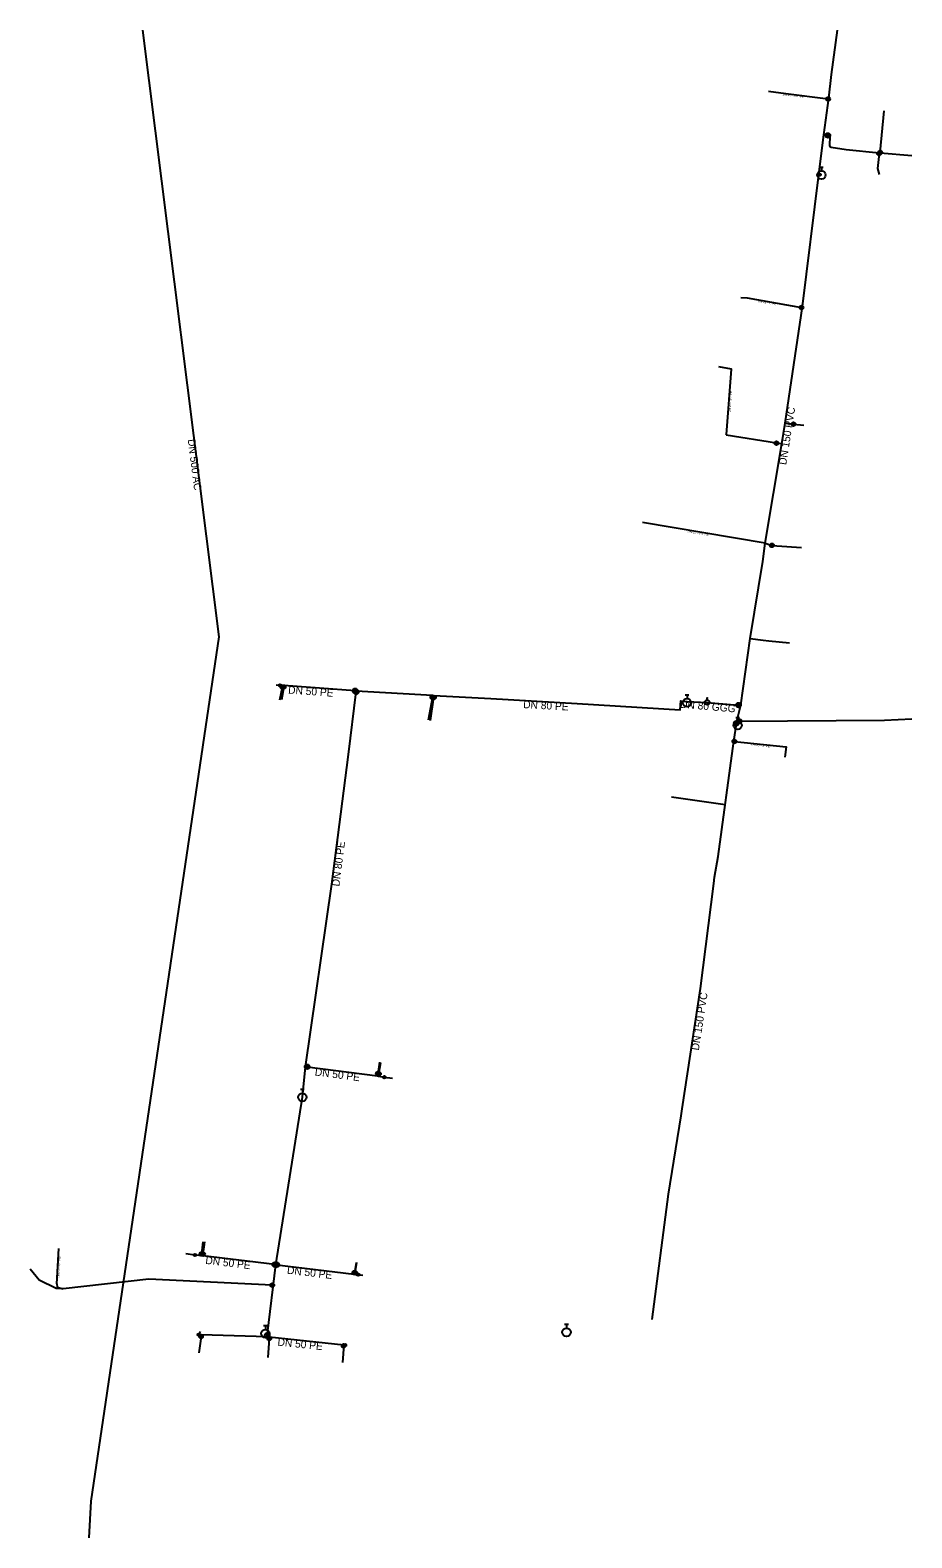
# Model space of a CAD drawing. Extents: x -463725 to -463539, y -1094944 to -1094626.
import ezdxf

# ---------------------------------------------------------------- set-up
doc = ezdxf.new("R2010")
doc.units = 0
for name, color, linetype in [('_hydrantova_odbocka_', 7, 'Continuous'), ('_kalosvod_', 7, 'Continuous'), ('_pripojka_prevzato_z_dokumentace_', 7, 'Continuous'), ('_pripojka_priblizne_', 7, 'Continuous'), ('_voda_provozovana_prevzato_z_dokumentace_', 7, 'Continuous'), ('_voda_smvak_prevzato_z_dokumentace_', 7, 'Continuous'), ('_voda_smvak_priblizne_', 7, 'Continuous'), ('Default', 7, 'Continuous'), ('MoLevel 2', 7, 'Continuous'), ('MoLevel 27', 7, 'Continuous'), ('MoLevel 28', 7, 'Continuous'), ('MoLevel 32', 7, 'Continuous'), ('MoLevel 38', 7, 'Continuous'), ('MoLevel 46', 7, 'Continuous'), ('MoLevel 48', 7, 'Continuous'), ('MoLevel 53', 7, 'Continuous'), ('MoLevel 55', 7, 'Continuous')]:
    doc.layers.add(name, color=color, linetype=linetype)

# ---------------------------------------------------------------- blocks, each defined once
blk = doc.blocks.new('_uzaver_')
at = {"layer": 'Default'}
for p, q in [((-0.000035, -0.000035), (0.000035, 0.000035)), ((0.000035, -0.000035), (-0.000035, 0.000035))]:
    blk.add_line(p, q, dxfattribs=at)
for radius in [0.00005, 0.0000025]:
    blk.add_circle((0, 0), radius, dxfattribs=at)
blk = doc.blocks.new('_uzaver_pripojka_')
at = {"layer": 'Default'}
for p, q in [((-0.000035, -0.000035), (0.000035, 0.000035)), ((0.000035, -0.000035), (-0.000035, 0.000035))]:
    blk.add_line(p, q, dxfattribs=at)
for radius in [0.00005, 0.0000025]:
    blk.add_circle((0, 0), radius, dxfattribs=at)
blk = doc.blocks.new('_hydrant_voda_')
at = {"layer": 'Default'}
for p, q in [((-0.000023, 0.000095), (0.000023, 0.000095)), ((0, 0.000095), (0, 0.00005))]:
    blk.add_line(p, q, dxfattribs=at)
blk.add_circle((0, 0), 0.00005, dxfattribs=at)
blk = doc.blocks.new('_vzdusnik_')
at = {"layer": 'Default'}
blk.add_line((0, 0.000095), (0.00001, 0.00008), dxfattribs=at)
blk.add_lwpolyline([(0, 0.00005), (0, 0.000095), (-0.00001, 0.00008)], dxfattribs=at)
blk.add_circle((0, 0), 0.00005, dxfattribs=at)

msp = doc.modelspace()

# ---------------------------------------------------------------- linework, layer by layer
at = {"layer": '_hydrantova_odbocka_'}
for p, q in [((-463586.45, -1094767.8), (-463586.43, -1094767.5)), ((-463674.74, -1094900.54), (-463675.17, -1094900.52))]:
    msp.add_line(p, q, dxfattribs=at)
for points in [[(-463558.72, -1094656.64), (-463558.51, -1094656.66), (-463558.18, -1094656.74)], [(-463575.79, -1094772.54), (-463575.88, -1094772.31), (-463576.05, -1094772.27)]]:
    msp.add_lwpolyline(points, dxfattribs=at)
at = {"layer": '_kalosvod_'}
for p, q in [((-463672.11, -1094764.13), (-463672.88, -1094764.11)), ((-463650.15, -1094846.58), (-463648.43, -1094846.77)), ((-463689.98, -1094884), (-463691.88, -1094883.76)), ((-463655.64, -1094888.11), (-463654.64, -1094888.22)), ((-463689.19, -1094900.76), (-463688.81, -1094900.12)), ((-463658.41, -1094902.91), (-463657.96, -1094902.96))]:
    msp.add_line(p, q, dxfattribs=at)
at = {"layer": '_pripojka_prevzato_z_dokumentace_'}
for p, q in [((-463569.33, -1094639.1), (-463565.69, -1094639.58)), ((-463570.01, -1094734.19), (-463595.85, -1094729.87)), ((-463567.55, -1094734.76), (-463562.38, -1094735.14)), ((-463573.18, -1094754.3), (-463570.43, -1094754.63)), ((-463719.04, -1094890.09), (-463718.59, -1094882.6)), ((-463658.68, -1094902.88), (-463658.94, -1094906.64))]:
    msp.add_line(p, q, dxfattribs=at)
for points in [[(-463565.69, -1094639.58), (-463556.76, -1094640.75), (-463556.61, -1094640.58)], [(-463575.12, -1094682.49), (-463573.77, -1094682.62), (-463562.35, -1094684.61), (-463562.17, -1094684.41)], [(-463578.23, -1094711.52), (-463578.11, -1094711.33), (-463577.08, -1094697.59), (-463579.74, -1094697.09)], [(-463565.82, -1094708.98), (-463564.07, -1094709.16), (-463561.86, -1094709.41)], [(-463566.5, -1094713.31), (-463567.65, -1094713.17), (-463578.23, -1094711.52)], [(-463570.01, -1094734.19), (-463568.58, -1094734.68), (-463567.55, -1094734.76)], [(-463672.12, -1094767.15), (-463671.59, -1094764.48), (-463671.58, -1094764.16)], [(-463671.28, -1094764.18), (-463671.31, -1094764.46), (-463671.75, -1094767.2)], [(-463640, -1094766.22), (-463640.03, -1094766.65), (-463640.92, -1094771.44)], [(-463640.39, -1094771.51), (-463639.7, -1094766.67), (-463639.73, -1094766.24)], [(-463651.16, -1094843.44), (-463651.49, -1094845.82), (-463651.6, -1094846.33)], [(-463651.35, -1094846.37), (-463651.26, -1094845.89), (-463650.84, -1094843.49)], [(-463688.34, -1094881.2), (-463688.61, -1094883.77), (-463688.66, -1094884.14)], [(-463688.29, -1094884.18), (-463688.26, -1094883.81), (-463687.88, -1094881.26)], [(-463719.19, -1094891.07), (-463722.76, -1094889.29), (-463724.65, -1094886.98)], [(-463656.05, -1094885.57), (-463656.44, -1094887.71), (-463656.5, -1094888)], [(-463656.3, -1094888.03), (-463656.25, -1094887.74), (-463655.94, -1094885.58)], [(-463688.65, -1094900.78), (-463688.7, -1094901.15), (-463689.17, -1094904.59)], [(-463674.34, -1094901.25), (-463674.34, -1094901.56), (-463674.62, -1094905.58)]]:
    msp.add_lwpolyline(points, dxfattribs=at)
at = {"layer": '_pripojka_priblizne_'}
for p, q in [((-463589.75, -1094787.6), (-463578.4, -1094789.2)), ((-463717.73, -1094891.11), (-463719.19, -1094891.07))]:
    msp.add_line(p, q, dxfattribs=at)
for points in [[(-463545.81, -1094652.1), (-463545.8, -1094651.99), (-463544.94, -1094643.26)], [(-463546.02, -1094652.08), (-463546.04, -1094652.24), (-463546.35, -1094655.34), (-463545.99, -1094656.63)], [(-463570.43, -1094754.63), (-463569.22, -1094754.77), (-463564.92, -1094755.17)], [(-463576.57, -1094775.91), (-463576.49, -1094775.92), (-463565.6, -1094777.09), (-463565.85, -1094779.26)], [(-463719.04, -1094890.09), (-463718.99, -1094890.78), (-463717.73, -1094891.11)], [(-463673.5, -1094890.37), (-463673.71, -1094890.34), (-463699.66, -1094889.06), (-463717.73, -1094891.11)]]:
    msp.add_lwpolyline(points, dxfattribs=at)
at = {"layer": '_voda_provozovana_prevzato_z_dokumentace_'}
for p, q in [((-463656.25, -1094765.28), (-463656.04, -1094765.3)), ((-463656.05, -1094765.52), (-463656.04, -1094765.3)), ((-463575.62, -1094768.28), (-463575.11, -1094768.31)), ((-463667.38, -1094850.81), (-463666.74, -1094844.39)), ((-463666.74, -1094844.39), (-463666.38, -1094844.38)), ((-463672.98, -1094886.04), (-463667.38, -1094850.81)), ((-463673.19, -1094886.01), (-463672.98, -1094886.04)), ((-463672.98, -1094886.04), (-463672.76, -1094886.06)), ((-463674.79, -1094901.23), (-463674.77, -1094900.93))]:
    msp.add_line(p, q, dxfattribs=at)
for points in [[(-463656.25, -1094765.28), (-463671.28, -1094764.18), (-463671.58, -1094764.16), (-463672.11, -1094764.13)], [(-463666.74, -1094844.39), (-463661.16, -1094805.99), (-463657.64, -1094778.67), (-463656.05, -1094765.52)], [(-463656.04, -1094765.3), (-463640, -1094766.22), (-463639.73, -1094766.24), (-463627.75, -1094766.93), (-463609.56, -1094767.92), (-463587.87, -1094769.27), (-463587.72, -1094767.41), (-463586.43, -1094767.5)], [(-463586.43, -1094767.5), (-463582.24, -1094767.72), (-463575.62, -1094768.28)], [(-463666.38, -1094844.38), (-463651.6, -1094846.33), (-463651.35, -1094846.37), (-463650.15, -1094846.58)], [(-463673.19, -1094886.01), (-463688.29, -1094884.18), (-463689.98, -1094884)], [(-463674.77, -1094900.93), (-463674.74, -1094900.54), (-463672.98, -1094886.04)], [(-463672.76, -1094886.06), (-463656.5, -1094888), (-463656.3, -1094888.03), (-463655.64, -1094888.11)], [(-463674.79, -1094901.23), (-463688.65, -1094900.78), (-463689.19, -1094900.76)], [(-463674.79, -1094901.23), (-463674.34, -1094901.25), (-463658.68, -1094902.88), (-463658.41, -1094902.91)]]:
    msp.add_lwpolyline(points, dxfattribs=at)
at = {"layer": '_voda_smvak_prevzato_z_dokumentace_'}
for p, q in [((-463558.72, -1094656.64), (-463557.68, -1094648.28)), ((-463556.8, -1094648.41), (-463557.68, -1094648.28)), ((-463575.87, -1094771.39), (-463575.11, -1094768.31)), ((-463576.09, -1094772.13), (-463575.87, -1094771.39)), ((-463576.05, -1094772.27), (-463576.09, -1094772.13)), ((-463575.87, -1094771.39), (-463575.5, -1094771.68))]:
    msp.add_line(p, q, dxfattribs=at)
for points in [[(-463557.68, -1094648.28), (-463556.61, -1094640.58), (-463556.06, -1094635.59), (-463554.76, -1094626.26)], [(-463556.8, -1094648.41), (-463556.41, -1094648.54), (-463556.47, -1094650.53), (-463556.4, -1094650.75), (-463556.15, -1094650.87), (-463552.96, -1094651.37), (-463546.02, -1094652.08), (-463545.81, -1094652.1), (-463539.15, -1094652.64)], [(-463575.11, -1094768.31), (-463573.18, -1094754.3), (-463570.51, -1094738.09), (-463570.01, -1094734.19), (-463566.5, -1094713.31), (-463565.82, -1094708.98), (-463562.17, -1094684.41), (-463558.72, -1094656.64)], [(-463575.5, -1094771.68), (-463544.89, -1094771.45), (-463539.15, -1094771.16)], [(-463593.75, -1094897.6), (-463590.34, -1094871.22), (-463587.66, -1094854.7), (-463587.46, -1094853.23), (-463583.58, -1094827.92), (-463580.81, -1094805.85), (-463580.66, -1094804.49), (-463579.91, -1094800.17), (-463576.57, -1094775.91), (-463576.05, -1094772.27)]]:
    msp.add_lwpolyline(points, dxfattribs=at)
at = {"layer": '_voda_smvak_priblizne_'}
msp.add_line((-463712.25, -1094943.51), (-463711.83, -1094935.76), dxfattribs=at)
msp.add_lwpolyline([(-463711.83, -1094935.76), (-463684.88, -1094753.92), (-463700.98, -1094626.26)], dxfattribs=at)

# ---------------------------------------------------------------- block references
at = {"layer": 'MoLevel 27'}
for p, xscale, yscale in [((-463556.8, -1094648.41), 10000, 10000), ((-463672.11, -1094764.13), 5000, 5000), ((-463656.25, -1094765.28), 10000, 10000), ((-463575.62, -1094768.28), 10000, 10000), ((-463666.38, -1094844.38), 10000, 10000), ((-463650.15, -1094846.58), 5000, 5000), ((-463689.98, -1094884), 5000, 5000), ((-463673.19, -1094886.01), 10000, 10000), ((-463672.76, -1094886.06), 10000, 10000), ((-463655.64, -1094888.11), 5000, 5000), ((-463689.19, -1094900.76), 5000, 5000), ((-463658.41, -1094902.91), 5000, 5000)]:
    msp.add_blockref('_uzaver_', p, dxfattribs=dict(at, xscale=xscale, yscale=yscale))
for p, xscale, yscale, rotation in [((-463558.51, -1094656.66), 5000, 5000, -17.292449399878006), ((-463656.05, -1094765.52), 10000, 9999.999999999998, -91.26280138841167), ((-463575.5, -1094771.68), 10000.000000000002, 9999.999999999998, 0.43461422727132), ((-463576.09, -1094772.13), 10000, 9999.999999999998, -95.027543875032), ((-463674.77, -1094900.93), 9999.999999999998, 10000.000000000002, -94.56151306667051)]:
    msp.add_blockref('_uzaver_', p, dxfattribs=dict(at, xscale=xscale, yscale=yscale, rotation=rotation))
at = {"layer": 'MoLevel 28', "xscale": 17636.68430335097, "yscale": 17636.68430335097}
for p in [(-463558.18, -1094656.74), (-463586.45, -1094767.8), (-463575.79, -1094772.54), (-463667.38, -1094850.81), (-463675.17, -1094900.52), (-463611.81, -1094900.25)]:
    msp.add_blockref('_hydrant_voda_', p, dxfattribs=at)
at = {"layer": 'MoLevel 38', "xscale": 10000, "yscale": 10000}
msp.add_blockref('_vzdusnik_', (-463582.24, -1094767.72), dxfattribs=at)
at = {"layer": 'MoLevel 53', "xscale": 7999.999999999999, "yscale": 7999.999999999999}
for p in [(-463556.76, -1094640.75), (-463546.04, -1094652.24), (-463545.8, -1094651.99), (-463562.35, -1094684.61), (-463564.07, -1094709.16), (-463567.65, -1094713.17), (-463568.58, -1094734.68), (-463671.59, -1094764.48), (-463671.31, -1094764.46), (-463640.03, -1094766.65), (-463639.7, -1094766.67), (-463576.49, -1094775.92), (-463651.49, -1094845.82), (-463651.26, -1094845.89), (-463688.61, -1094883.77), (-463688.26, -1094883.81), (-463656.44, -1094887.71), (-463656.25, -1094887.74), (-463673.71, -1094890.34), (-463688.7, -1094901.15), (-463674.34, -1094901.56), (-463658.7, -1094903.12)]:
    msp.add_blockref('_uzaver_pripojka_', p, dxfattribs=at)

# ---------------------------------------------------------------- texts
at = {"layer": 'MoLevel 2'}
msp.add_text('DN 500 AC', height=1.605, rotation=277.1894, dxfattribs=at).set_placement((-463691.5, -1094712.41))
at = {"layer": 'MoLevel 32'}
msp.add_text("DN 25 - 1'' PE", height=0.455, rotation=353.8487, dxfattribs=at).set_placement((-463572.96, -1094776.76))
at = {"layer": 'MoLevel 46'}
for rotation, p in [(81.0491, (-463565.59, -1094717.83)), (81.2845, (-463583.97, -1094841.03))]:
    msp.add_text('DN 150 PVC', height=1.605, rotation=rotation, dxfattribs=at).set_placement(p)
at = {"layer": 'MoLevel 48'}
for s, rotation, p in [('DN 50 PE', 355.8153, (-463670.41, -1094765.85)), ('DN 80 PE', 356.8847, (-463620.95, -1094768.91)), ('DN 80 GGG', 355.1274, (-463587.95, -1094768.84)), ('DN 80 PE', 82.6583, (-463659.61, -1094806.51)), ('DN 50 PE', 352.4841, (-463664.83, -1094846.2)), ('DN 50 PE', 353.0899, (-463687.85, -1094885.85)), ('DN 50 PE', 353.1961, (-463670.68, -1094887.92)), ('DN 50 PE', 354.0493, (-463672.66, -1094903.04))]:
    msp.add_text(s, height=1.605, rotation=rotation, dxfattribs=at).set_placement(p)
at = {"layer": 'MoLevel 55'}
for s, rotation, p in [("DN 20 - 3/4'' PE", 352.5218, (-463566.35, -1094639.95)), ("DN 25 - 1'' PE", 350.1151, (-463571.57, -1094683.47)), ("DN 20 - 3/4'' PE", 85.7129, (-463577.3, -1094706.64)), ("DN 32 - 5/4'' PE", 350.5089, (-463586.35, -1094731.92)), ("DN 20 - 3/4'' PE", 86.5886, (-463718.5, -1094888.79))]:
    msp.add_text(s, height=0.455, rotation=rotation, dxfattribs=at).set_placement(p)

doc.saveas('drawing.dxf')
